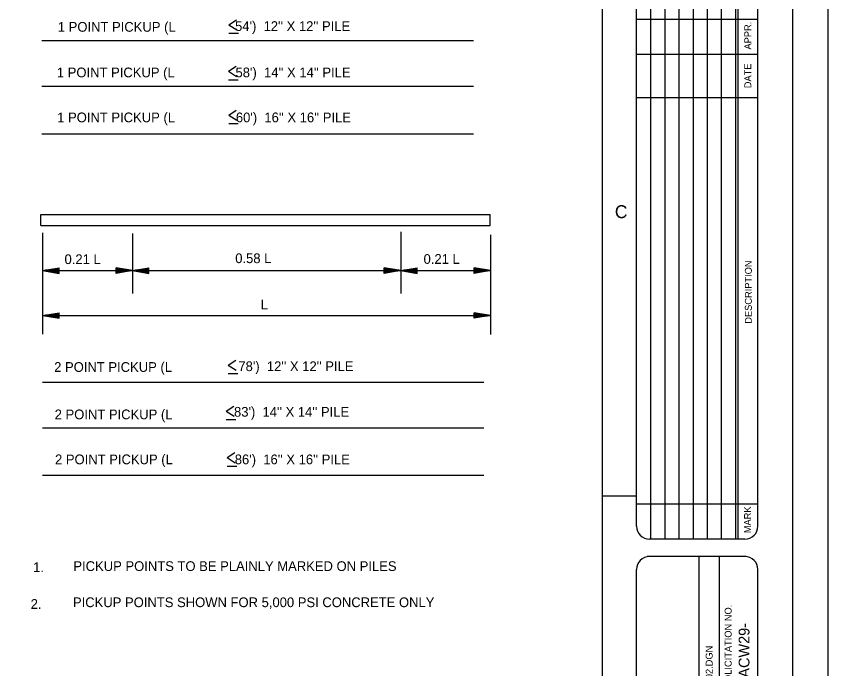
# Model space of a CAD drawing. Extents: x 44742.26 to 44749.63, y 44739 to 44741.19.
# Drawn here: x 44744.335 to 44745.087, y 44739.935 to 44740.541 of the extents above; entities that cross this region are included whole.
import ezdxf

# ---------------------------------------------------------------- set-up
doc = ezdxf.new("R2010")
doc.units = 0
for name, color, linetype in [('Level 1', 7, 'Continuous'), ('Level 10', 7, 'Continuous'), ('Level 2', 7, 'Continuous'), ('Level 4', 7, 'Continuous'), ('Level 7', 7, 'Continuous'), ('Level 9', 7, 'Continuous'), ('S-ANNO-DIMS', 7, 'Continuous')]:
    doc.layers.add(name, color=color, linetype=linetype)

msp = doc.modelspace()

# ---------------------------------------------------------------- linework, layer by layer
at = {"layer": 'Level 1'}
for p, q in [((44744.92303, 44741.01948), (44744.92303, 44740.0556)), ((44744.93613, 44741.01948), (44744.93613, 44740.0556)), ((44744.94924, 44741.01948), (44744.94924, 44740.0556)), ((44744.96235, 44741.01948), (44744.96235, 44740.0556)), ((44744.97546, 44741.01948), (44744.97546, 44740.0556)), ((44744.98857, 44741.01948), (44744.98857, 44740.0556)), ((44745.00168, 44741.01948), (44745.00168, 44740.0556)), ((44745.00399, 44741.01948), (44745.00399, 44740.0556)), ((44745.0225, 44740.53754), (44744.90992, 44740.53754)), ((44744.35929, 44740.33962), (44744.35929, 44740.24554)), ((44744.44259, 44740.339), (44744.44259, 44740.28335)), ((44744.69132, 44740.3405), (44744.69132, 44740.28328)), ((44744.77462, 44740.33791), (44744.77462, 44740.24521)), ((44744.35929, 44740.30467), (44744.37453, 44740.30725)), ((44744.35929, 44740.30467), (44744.77462, 44740.30467)), ((44744.35929, 44740.30467), (44744.37453, 44740.30467)), ((44744.35929, 44740.30467), (44744.37453, 44740.30207)), ((44744.36208, 44740.30488), (44744.37386, 44740.30688)), ((44744.3742, 44740.30502), (44744.36208, 44740.30488)), ((44744.3742, 44740.30429), (44744.36208, 44740.30444)), ((44744.36208, 44740.30444), (44744.37386, 44740.30245)), ((44744.36543, 44740.30519), (44744.37351, 44740.30652)), ((44744.37384, 44740.30534), (44744.36543, 44740.30519)), ((44744.36543, 44740.30413), (44744.37351, 44740.30279)), ((44744.37384, 44740.30398), (44744.36543, 44740.30413)), ((44744.36867, 44740.30546), (44744.37318, 44740.30615)), ((44744.3735, 44740.30562), (44744.36867, 44740.30546)), ((44744.36867, 44740.30386), (44744.37318, 44740.30317)), ((44744.3735, 44740.30371), (44744.36867, 44740.30386)), ((44744.37319, 44740.30579), (44744.3718, 44740.30573)), ((44744.37319, 44740.30352), (44744.3718, 44740.30359)), ((44744.37318, 44740.30615), (44744.37319, 44740.30579)), ((44744.37318, 44740.30317), (44744.37319, 44740.30352)), ((44744.37351, 44740.30652), (44744.3735, 44740.30562)), ((44744.37351, 44740.30279), (44744.3735, 44740.30371)), ((44744.37386, 44740.30688), (44744.37384, 44740.30534)), ((44744.37386, 44740.30245), (44744.37384, 44740.30398)), ((44744.37419, 44740.30688), (44744.3742, 44740.30502)), ((44744.37419, 44740.30245), (44744.3742, 44740.30429)), ((44744.37453, 44740.30207), (44744.37453, 44740.30725)), ((44744.42735, 44740.30207), (44744.42735, 44740.30725)), ((44744.44259, 44740.30467), (44744.42735, 44740.30725)), ((44744.44259, 44740.30467), (44744.42735, 44740.30467)), ((44744.44259, 44740.30467), (44744.42735, 44740.30207)), ((44744.42768, 44740.30688), (44744.42767, 44740.30502)), ((44744.42767, 44740.30502), (44744.4398, 44740.30488)), ((44744.42767, 44740.30429), (44744.4398, 44740.30444)), ((44744.42768, 44740.30245), (44744.42767, 44740.30429)), ((44744.4398, 44740.30488), (44744.42802, 44740.30688)), ((44744.42802, 44740.30688), (44744.42804, 44740.30534)), ((44744.4398, 44740.30444), (44744.42802, 44740.30245)), ((44744.42802, 44740.30245), (44744.42804, 44740.30398)), ((44744.42804, 44740.30534), (44744.43644, 44740.30519)), ((44744.42804, 44740.30398), (44744.43644, 44740.30413)), ((44744.43644, 44740.30519), (44744.42838, 44740.30652)), ((44744.42838, 44740.30652), (44744.42839, 44740.30562)), ((44744.43644, 44740.30413), (44744.42838, 44740.30279)), ((44744.42838, 44740.30279), (44744.42839, 44740.30371)), ((44744.42839, 44740.30562), (44744.4332, 44740.30546)), ((44744.42839, 44740.30371), (44744.4332, 44740.30386)), ((44744.42869, 44740.30615), (44744.42868, 44740.30579)), ((44744.42868, 44740.30579), (44744.43009, 44740.30573)), ((44744.42868, 44740.30352), (44744.43009, 44740.30359)), ((44744.42869, 44740.30317), (44744.42868, 44740.30352)), ((44744.4332, 44740.30546), (44744.42869, 44740.30615)), ((44744.4332, 44740.30386), (44744.42869, 44740.30317)), ((44744.44259, 44740.30467), (44744.45783, 44740.30725)), ((44744.44259, 44740.30467), (44744.45783, 44740.30467)), ((44744.44259, 44740.30467), (44744.45783, 44740.30207)), ((44744.44538, 44740.30488), (44744.45716, 44740.30688)), ((44744.45751, 44740.30502), (44744.44538, 44740.30488)), ((44744.45751, 44740.30429), (44744.44538, 44740.30444)), ((44744.44538, 44740.30444), (44744.45716, 44740.30245)), ((44744.44874, 44740.30519), (44744.4568, 44740.30652)), ((44744.45714, 44740.30534), (44744.44874, 44740.30519)), ((44744.44874, 44740.30413), (44744.4568, 44740.30279)), ((44744.45714, 44740.30398), (44744.44874, 44740.30413)), ((44744.45198, 44740.30546), (44744.45649, 44740.30615)), ((44744.45679, 44740.30562), (44744.45198, 44740.30546)), ((44744.45198, 44740.30386), (44744.45649, 44740.30317)), ((44744.45679, 44740.30371), (44744.45198, 44740.30386)), ((44744.4565, 44740.30579), (44744.45509, 44740.30573)), ((44744.4565, 44740.30352), (44744.45509, 44740.30359)), ((44744.45649, 44740.30615), (44744.4565, 44740.30579)), ((44744.45649, 44740.30317), (44744.4565, 44740.30352)), ((44744.4568, 44740.30652), (44744.45679, 44740.30562)), ((44744.4568, 44740.30279), (44744.45679, 44740.30371)), ((44744.45716, 44740.30688), (44744.45714, 44740.30534)), ((44744.45716, 44740.30245), (44744.45714, 44740.30398)), ((44744.4575, 44740.30688), (44744.45751, 44740.30502)), ((44744.4575, 44740.30245), (44744.45751, 44740.30429)), ((44744.45783, 44740.30207), (44744.45783, 44740.30725)), ((44744.67609, 44740.30207), (44744.67609, 44740.30725)), ((44744.69132, 44740.30467), (44744.67609, 44740.30725)), ((44744.69132, 44740.30467), (44744.67609, 44740.30467)), ((44744.69132, 44740.30467), (44744.67609, 44740.30207)), ((44744.67641, 44740.30688), (44744.67639, 44740.30502)), ((44744.67639, 44740.30502), (44744.68854, 44740.30488)), ((44744.67639, 44740.30429), (44744.68854, 44740.30444)), ((44744.67641, 44740.30245), (44744.67639, 44740.30429)), ((44744.68854, 44740.30488), (44744.67676, 44740.30688)), ((44744.67676, 44740.30688), (44744.67677, 44740.30534)), ((44744.68854, 44740.30444), (44744.67676, 44740.30245)), ((44744.67676, 44740.30245), (44744.67677, 44740.30398)), ((44744.67677, 44740.30534), (44744.68517, 44740.30519)), ((44744.67677, 44740.30398), (44744.68517, 44740.30413)), ((44744.68517, 44740.30519), (44744.67711, 44740.30652)), ((44744.67711, 44740.30652), (44744.67712, 44740.30562)), ((44744.68517, 44740.30413), (44744.67711, 44740.30279)), ((44744.67711, 44740.30279), (44744.67712, 44740.30371)), ((44744.67712, 44740.30562), (44744.68192, 44740.30546)), ((44744.67712, 44740.30371), (44744.68192, 44740.30386)), ((44744.68192, 44740.30546), (44744.67742, 44740.30615)), ((44744.67742, 44740.30615), (44744.67742, 44740.30579)), ((44744.67742, 44740.30579), (44744.67882, 44740.30573)), ((44744.68192, 44740.30386), (44744.67742, 44740.30317)), ((44744.67742, 44740.30352), (44744.67882, 44740.30359)), ((44744.67742, 44740.30317), (44744.67742, 44740.30352)), ((44744.69132, 44740.30467), (44744.70656, 44740.30725)), ((44744.69132, 44740.30467), (44744.70656, 44740.30467)), ((44744.69132, 44740.30467), (44744.70656, 44740.30207)), ((44744.69411, 44740.30488), (44744.70589, 44740.30688)), ((44744.70625, 44740.30502), (44744.69411, 44740.30488)), ((44744.70625, 44740.30429), (44744.69411, 44740.30444)), ((44744.69411, 44740.30444), (44744.70589, 44740.30245)), ((44744.69747, 44740.30519), (44744.70554, 44740.30652)), ((44744.70588, 44740.30534), (44744.69747, 44740.30519)), ((44744.69747, 44740.30413), (44744.70554, 44740.30279)), ((44744.70588, 44740.30398), (44744.69747, 44740.30413)), ((44744.70072, 44740.30546), (44744.70522, 44740.30615)), ((44744.70553, 44740.30562), (44744.70072, 44740.30546)), ((44744.70072, 44740.30386), (44744.70522, 44740.30317)), ((44744.70553, 44740.30371), (44744.70072, 44740.30386)), ((44744.70522, 44740.30579), (44744.70382, 44740.30573)), ((44744.70522, 44740.30352), (44744.70382, 44740.30359)), ((44744.70522, 44740.30615), (44744.70522, 44740.30579)), ((44744.70522, 44740.30317), (44744.70522, 44740.30352)), ((44744.70554, 44740.30652), (44744.70553, 44740.30562)), ((44744.70554, 44740.30279), (44744.70553, 44740.30371)), ((44744.70589, 44740.30688), (44744.70588, 44740.30534)), ((44744.70589, 44740.30245), (44744.70588, 44740.30398)), ((44744.70623, 44740.30688), (44744.70625, 44740.30502)), ((44744.70623, 44740.30245), (44744.70625, 44740.30429)), ((44744.70656, 44740.30207), (44744.70656, 44740.30725)), ((44744.75939, 44740.30207), (44744.75939, 44740.30725)), ((44744.77462, 44740.30467), (44744.75939, 44740.30725)), ((44744.77462, 44740.30467), (44744.75939, 44740.30467)), ((44744.77462, 44740.30467), (44744.75939, 44740.30207)), ((44744.75972, 44740.30688), (44744.75969, 44740.30502)), ((44744.75969, 44740.30502), (44744.77183, 44740.30488)), ((44744.75969, 44740.30429), (44744.77183, 44740.30444)), ((44744.75972, 44740.30245), (44744.75969, 44740.30429)), ((44744.77183, 44740.30488), (44744.76006, 44740.30688)), ((44744.76006, 44740.30688), (44744.76006, 44740.30534)), ((44744.76006, 44740.30534), (44744.76848, 44740.30519)), ((44744.77183, 44740.30444), (44744.76006, 44740.30245)), ((44744.76006, 44740.30398), (44744.76848, 44740.30413)), ((44744.76006, 44740.30245), (44744.76006, 44740.30398)), ((44744.76848, 44740.30519), (44744.76041, 44740.30652)), ((44744.76041, 44740.30652), (44744.76042, 44740.30562)), ((44744.76848, 44740.30413), (44744.76041, 44740.30279)), ((44744.76041, 44740.30279), (44744.76042, 44740.30371)), ((44744.76042, 44740.30562), (44744.76523, 44740.30546)), ((44744.76042, 44740.30371), (44744.76523, 44740.30386)), ((44744.76523, 44740.30546), (44744.76073, 44740.30615)), ((44744.76073, 44740.30615), (44744.76073, 44740.30579)), ((44744.76073, 44740.30579), (44744.76212, 44740.30573)), ((44744.76523, 44740.30386), (44744.76073, 44740.30317)), ((44744.76073, 44740.30352), (44744.76212, 44740.30359)), ((44744.76073, 44740.30317), (44744.76073, 44740.30352)), ((44744.35929, 44740.26301), (44744.37453, 44740.2656)), ((44744.35929, 44740.26301), (44744.77462, 44740.26301)), ((44744.35929, 44740.26301), (44744.37453, 44740.26301)), ((44744.35929, 44740.26301), (44744.37453, 44740.26043)), ((44744.36208, 44740.26323), (44744.37386, 44740.26522)), ((44744.3742, 44740.26338), (44744.36208, 44740.26323)), ((44744.3742, 44740.26265), (44744.36208, 44740.26279)), ((44744.36208, 44740.26279), (44744.37386, 44740.2608)), ((44744.36543, 44740.26354), (44744.37351, 44740.26488)), ((44744.37384, 44740.26369), (44744.36543, 44740.26354)), ((44744.36543, 44740.26248), (44744.37351, 44740.26115)), ((44744.37384, 44740.26234), (44744.36543, 44740.26248)), ((44744.36867, 44740.26381), (44744.37318, 44740.2645)), ((44744.3735, 44740.26396), (44744.36867, 44740.26381)), ((44744.36867, 44740.26221), (44744.37318, 44740.26152)), ((44744.3735, 44740.26205), (44744.36867, 44740.26221)), ((44744.37319, 44740.26415), (44744.3718, 44740.26409)), ((44744.37319, 44740.26188), (44744.3718, 44740.26194)), ((44744.37318, 44740.2645), (44744.37319, 44740.26415)), ((44744.37318, 44740.26152), (44744.37319, 44740.26188)), ((44744.37351, 44740.26488), (44744.3735, 44740.26396)), ((44744.37351, 44740.26115), (44744.3735, 44740.26205)), ((44744.37386, 44740.26522), (44744.37384, 44740.26369)), ((44744.37386, 44740.2608), (44744.37384, 44740.26234)), ((44744.37419, 44740.26522), (44744.3742, 44740.26338)), ((44744.37419, 44740.2608), (44744.3742, 44740.26265)), ((44744.37453, 44740.26043), (44744.37453, 44740.2656)), ((44744.75939, 44740.26043), (44744.75939, 44740.2656)), ((44744.77462, 44740.26301), (44744.75939, 44740.2656)), ((44744.77462, 44740.26301), (44744.75939, 44740.26301)), ((44744.77462, 44740.26301), (44744.75939, 44740.26043)), ((44744.75972, 44740.26522), (44744.75969, 44740.26338)), ((44744.75969, 44740.26338), (44744.77183, 44740.26323)), ((44744.75969, 44740.26265), (44744.77183, 44740.26279)), ((44744.75972, 44740.2608), (44744.75969, 44740.26265)), ((44744.77183, 44740.26323), (44744.76006, 44740.26522)), ((44744.76006, 44740.26522), (44744.76006, 44740.26369)), ((44744.76006, 44740.26369), (44744.76848, 44740.26354)), ((44744.77183, 44740.26279), (44744.76006, 44740.2608)), ((44744.76006, 44740.26234), (44744.76848, 44740.26248)), ((44744.76006, 44740.2608), (44744.76006, 44740.26234)), ((44744.76848, 44740.26354), (44744.76041, 44740.26488)), ((44744.76041, 44740.26488), (44744.76042, 44740.26396)), ((44744.76848, 44740.26248), (44744.76041, 44740.26115)), ((44744.76041, 44740.26115), (44744.76042, 44740.26205)), ((44744.76042, 44740.26396), (44744.76523, 44740.26381)), ((44744.76042, 44740.26205), (44744.76523, 44740.26221)), ((44744.76523, 44740.26381), (44744.76073, 44740.2645)), ((44744.76073, 44740.2645), (44744.76073, 44740.26415)), ((44744.76073, 44740.26415), (44744.76212, 44740.26409)), ((44744.76523, 44740.26221), (44744.76073, 44740.26152)), ((44744.76073, 44740.26188), (44744.76212, 44740.26194)), ((44744.76073, 44740.26152), (44744.76073, 44740.26188)), ((44745.01045, 44740.0556), (44744.92197, 44740.0556)), ((44745.0117, 44740.03941), (44744.91994, 44740.03941)), ((44744.96775, 44740.03941), (44744.96775, 44739.50118))]:
    msp.add_line(p, q, dxfattribs=at)
msp.add_lwpolyline([(44742.25988, 44741.18835), (44745.08727, 44741.18835), (44745.08727, 44739.00305), (44742.25988, 44739.00305)], close=True, dxfattribs=at)
for points in [[(44744.90992, 44740.06765), (44744.90992, 44741.00743)], [(44745.0225, 44740.06765), (44745.0225, 44741.00743)], [(44745.01045, 44740.03941), (44744.92197, 44740.03941)], [(44744.90992, 44739.51323), (44744.90992, 44740.02736)], [(44745.0225, 44739.51323), (44745.0225, 44740.02736)]]:
    msp.add_lwpolyline(points, dxfattribs=at)
for centre, start, end in [((44744.92197, 44740.06765), 180, 270), ((44745.01045, 44740.06765), 270, 0), ((44744.92197, 44740.02736), 90, 180), ((44745.01045, 44740.02736), 0, 90)]:
    msp.add_arc(centre, 0.01205, start, end, dxfattribs=at)
at = {"layer": 'Level 10'}
for p, q in [((44744.35853, 44740.51792), (44744.75866, 44740.51792)), ((44744.35853, 44740.47564), (44744.75866, 44740.47564)), ((44744.35853, 44740.43155), (44744.75866, 44740.43155)), ((44744.35929, 44740.20113), (44744.76849, 44740.20113)), ((44744.35929, 44740.15885), (44744.76849, 44740.15885)), ((44744.35929, 44740.11476), (44744.76849, 44740.11476)), ((44744.8783, 44740.0957), (44744.90992, 44740.0957))]:
    msp.add_line(p, q, dxfattribs=at)
at = {"layer": 'Level 2'}
msp.add_line((44744.9867, 44740.03941), (44744.9867, 44739.7703), dxfattribs=at)
at = {"layer": 'Level 7'}
for p, q in [((44745.0225, 44740.50516), (44744.90992, 44740.50516)), ((44745.0225, 44740.46499), (44744.90992, 44740.46499)), ((44744.35769, 44740.35673), (44744.77419, 44740.35673)), ((44744.35769, 44740.34631), (44744.35769, 44740.35673)), ((44744.77419, 44740.34631), (44744.77419, 44740.35673)), ((44744.35769, 44740.34631), (44744.77419, 44740.34631)), ((44745.0225, 44740.08799), (44744.90992, 44740.08799))]:
    msp.add_line(p, q, dxfattribs=at)
at = {"layer": 'Level 9'}
msp.add_line((44745.05488, 44739.03544), (44745.05488, 44741.15596), dxfattribs=at)
msp.add_lwpolyline([(44744.8783, 44739.03544), (44744.8783, 44741.15596)], dxfattribs=at)
at = {"layer": 'S-ANNO-DIMS'}
for p, q in [((44744.53197, 44740.53263), (44744.53906, 44740.53723)), ((44744.53197, 44740.53263), (44744.53939, 44740.52782)), ((44744.53197, 44740.52473), (44744.54083, 44740.52473)), ((44744.53163, 44740.48958), (44744.53872, 44740.49418)), ((44744.53163, 44740.48958), (44744.53905, 44740.48476)), ((44744.53163, 44740.48167), (44744.54049, 44740.48167)), ((44744.5318, 44740.44889), (44744.53889, 44740.45349)), ((44744.5318, 44740.44889), (44744.53922, 44740.44408)), ((44744.5318, 44740.44099), (44744.54066, 44740.44099)), ((44744.53146, 44740.217), (44744.53855, 44740.2216)), ((44744.53146, 44740.217), (44744.53888, 44740.21218)), ((44744.53146, 44740.20909), (44744.54032, 44740.20909)), ((44744.52943, 44740.17428), (44744.53651, 44740.17888)), ((44744.52943, 44740.17428), (44744.53684, 44740.16947)), ((44744.52943, 44740.16638), (44744.53829, 44740.16638)), ((44744.53045, 44740.13122), (44744.53753, 44740.13583)), ((44744.53045, 44740.13122), (44744.53786, 44740.12641)), ((44744.53045, 44740.12332), (44744.53931, 44740.12332))]:
    msp.add_line(p, q, dxfattribs=at)

# ---------------------------------------------------------------- texts
at = {"layer": 'Level 1'}
for s, height, p in [('APPR.', 0.006426, (44745.01632, 44740.50963)), ('DATE', 0.006426, (44745.01633, 44740.47373)), ('DESCRIPTION', 0.0064257, (44745.01684, 44740.25532)), ('MARK', 0.006426, (44745.01611, 44740.06107)), ('SOLICITATION NO.', 0.0064263, (44744.9981, 44739.9174)), ('AETYP02.DGN', 0.0064258, (44744.9805, 44739.89754))]:
    msp.add_text(s, height=height, rotation=90, dxfattribs=at).set_placement(p)
msp.add_text('C', height=0.01203, dxfattribs=at).set_placement((44744.88987, 44740.35325))
at = {"layer": 'Level 10'}
for s, p in [('1 POINT PICKUP (L', (44744.3734, 44740.52613)), ("  54')  12'' X 12'' PILE", (44744.53102, 44740.52684)), ('1 POINT PICKUP (L', (44744.3725, 44740.48388)), ("  58')  14'' X 14'' PILE", (44744.53141, 44740.48388)), ('1 POINT PICKUP (L', (44744.3728, 44740.44217)), ("  60')  16'' X 16'' PILE", (44744.53176, 44740.44217)), ("  78')  12'' X 12'' PILE", (44744.53408, 44740.2114)), ('2 POINT PICKUP (L', (44744.37001, 44740.21069)), ('2 POINT PICKUP (L', (44744.37046, 44740.16675)), ("  83')  14'' X 14'' PILE", (44744.53005, 44740.16912)), ('2 POINT PICKUP (L', (44744.37077, 44740.12504)), ("  86')  16'' X 16'' PILE", (44744.53074, 44740.12503))]:
    msp.add_text(s, height=0.0090203, dxfattribs=at).set_placement(p)
at = {"layer": 'Level 4'}
for s, height, p in [('1.', 0.00902, (44744.35045, 44740.02503)), ('PICKUP POINTS TO BE PLAINLY MARKED ON PILES', 0.0090203, (44744.38783, 44740.02604)), ('2.', 0.00902, (44744.34822, 44739.99093)), ('PICKUP POINTS SHOWN FOR 5,000 PSI CONCRETE ONLY', 0.0090203, (44744.38742, 44739.99251))]:
    msp.add_text(s, height=height, dxfattribs=at).set_placement(p)
at = {"layer": 'Level 7'}
for s, p in [('0.21 L', (44744.3796, 44740.31066)), ('0.58 L', (44744.53788, 44740.31155)), ('0.21 L', (44744.71252, 44740.31087)), ('L', (44744.56154, 44740.2687))]:
    msp.add_text(s, height=0.00902, dxfattribs=at).set_placement(p)
msp.add_text('DACW29-', height=0.010024, rotation=90, dxfattribs=at).set_placement((44745.01468, 44739.91748))

doc.saveas('drawing.dxf')
